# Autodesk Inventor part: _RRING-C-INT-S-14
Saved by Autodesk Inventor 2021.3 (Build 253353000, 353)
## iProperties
Created: 2021-10
Part Number: _RRING-C-INT-S-14
Material: Generic
Document SubType Name: Modeling
Designer: Administrator
Density: 1 g/cm^3
Appearance: Default
Title: _RRING-C-INT-S-14
Author: Administrator
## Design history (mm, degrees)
feature "Body1"
body "Solid1"
